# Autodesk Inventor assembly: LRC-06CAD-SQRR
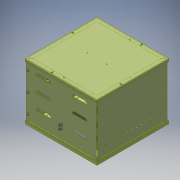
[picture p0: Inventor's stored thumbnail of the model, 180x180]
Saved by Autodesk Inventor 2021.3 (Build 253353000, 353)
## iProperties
Part Number: LRC-06CAD-SQRR
Document SubType Name: Assembly
Designer: JChurch
Author: JChurch
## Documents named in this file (6)
- X:\Revit Files\0000-Un-Zipped\COB\LRC-06CAD-SQR\LRC-06CAD-SQRR.iam
- X:\INVENTOR\830\830376-00-00.iam
- X:\INVENTOR\881\881035-00-00.iam
- X:\INVENTOR\830\830402-00-00.ipt
- X:\INVENTOR\KIRLIN_ENG\750\750055-00-XX.iam
- X:\INVENTOR\725\725267-00-00.ipt
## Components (5 placed, 5 different names)
1. 830376-00-00:1 [sub-assembly] — Mate:1, Mate:2, Flush:1, Mate:3, Angle:1, Mate:7
2. 881035-00-00:1 [sub-assembly] — Mate:3, Mate:4, Angle:1, Mate:5, Angle:2
3. 830402-00-00:1 — Mate:5, Mate:6, Angle:2
4. 750055-00-XX:1 [sub-assembly] — Mate:7, Mate:8, Mate:9, Mate:10, Mate:11, Mate:12
5. 725267-00-00:1 — Mate:10, Mate:11, Mate:12
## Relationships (15: Mate 12, Angle 2, Flush 1)
- Mate:1: 830376-00-00:1
- Mate:2: 830376-00-00:1
- Flush:1: 830376-00-00:1
- Mate:3: 830376-00-00:1 ↔ 881035-00-00:1
- Mate:4: 881035-00-00:1
- Angle:1: 830376-00-00:1 ↔ 881035-00-00:1
- Mate:5: 881035-00-00:1 ↔ 830402-00-00:1
- Mate:6: 830402-00-00:1
- Angle:2: 881035-00-00:1 ↔ 830402-00-00:1
- Mate:7: 830376-00-00:1 ↔ 750055-00-XX:1
- Mate:8: 750055-00-XX:1
- Mate:9: 750055-00-XX:1
- Mate:10: 750055-00-XX:1 ↔ 725267-00-00:1
- Mate:11: 750055-00-XX:1 ↔ 725267-00-00:1
- Mate:12: 750055-00-XX:1 ↔ 725267-00-00:1
